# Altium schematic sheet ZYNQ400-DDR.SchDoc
size A3
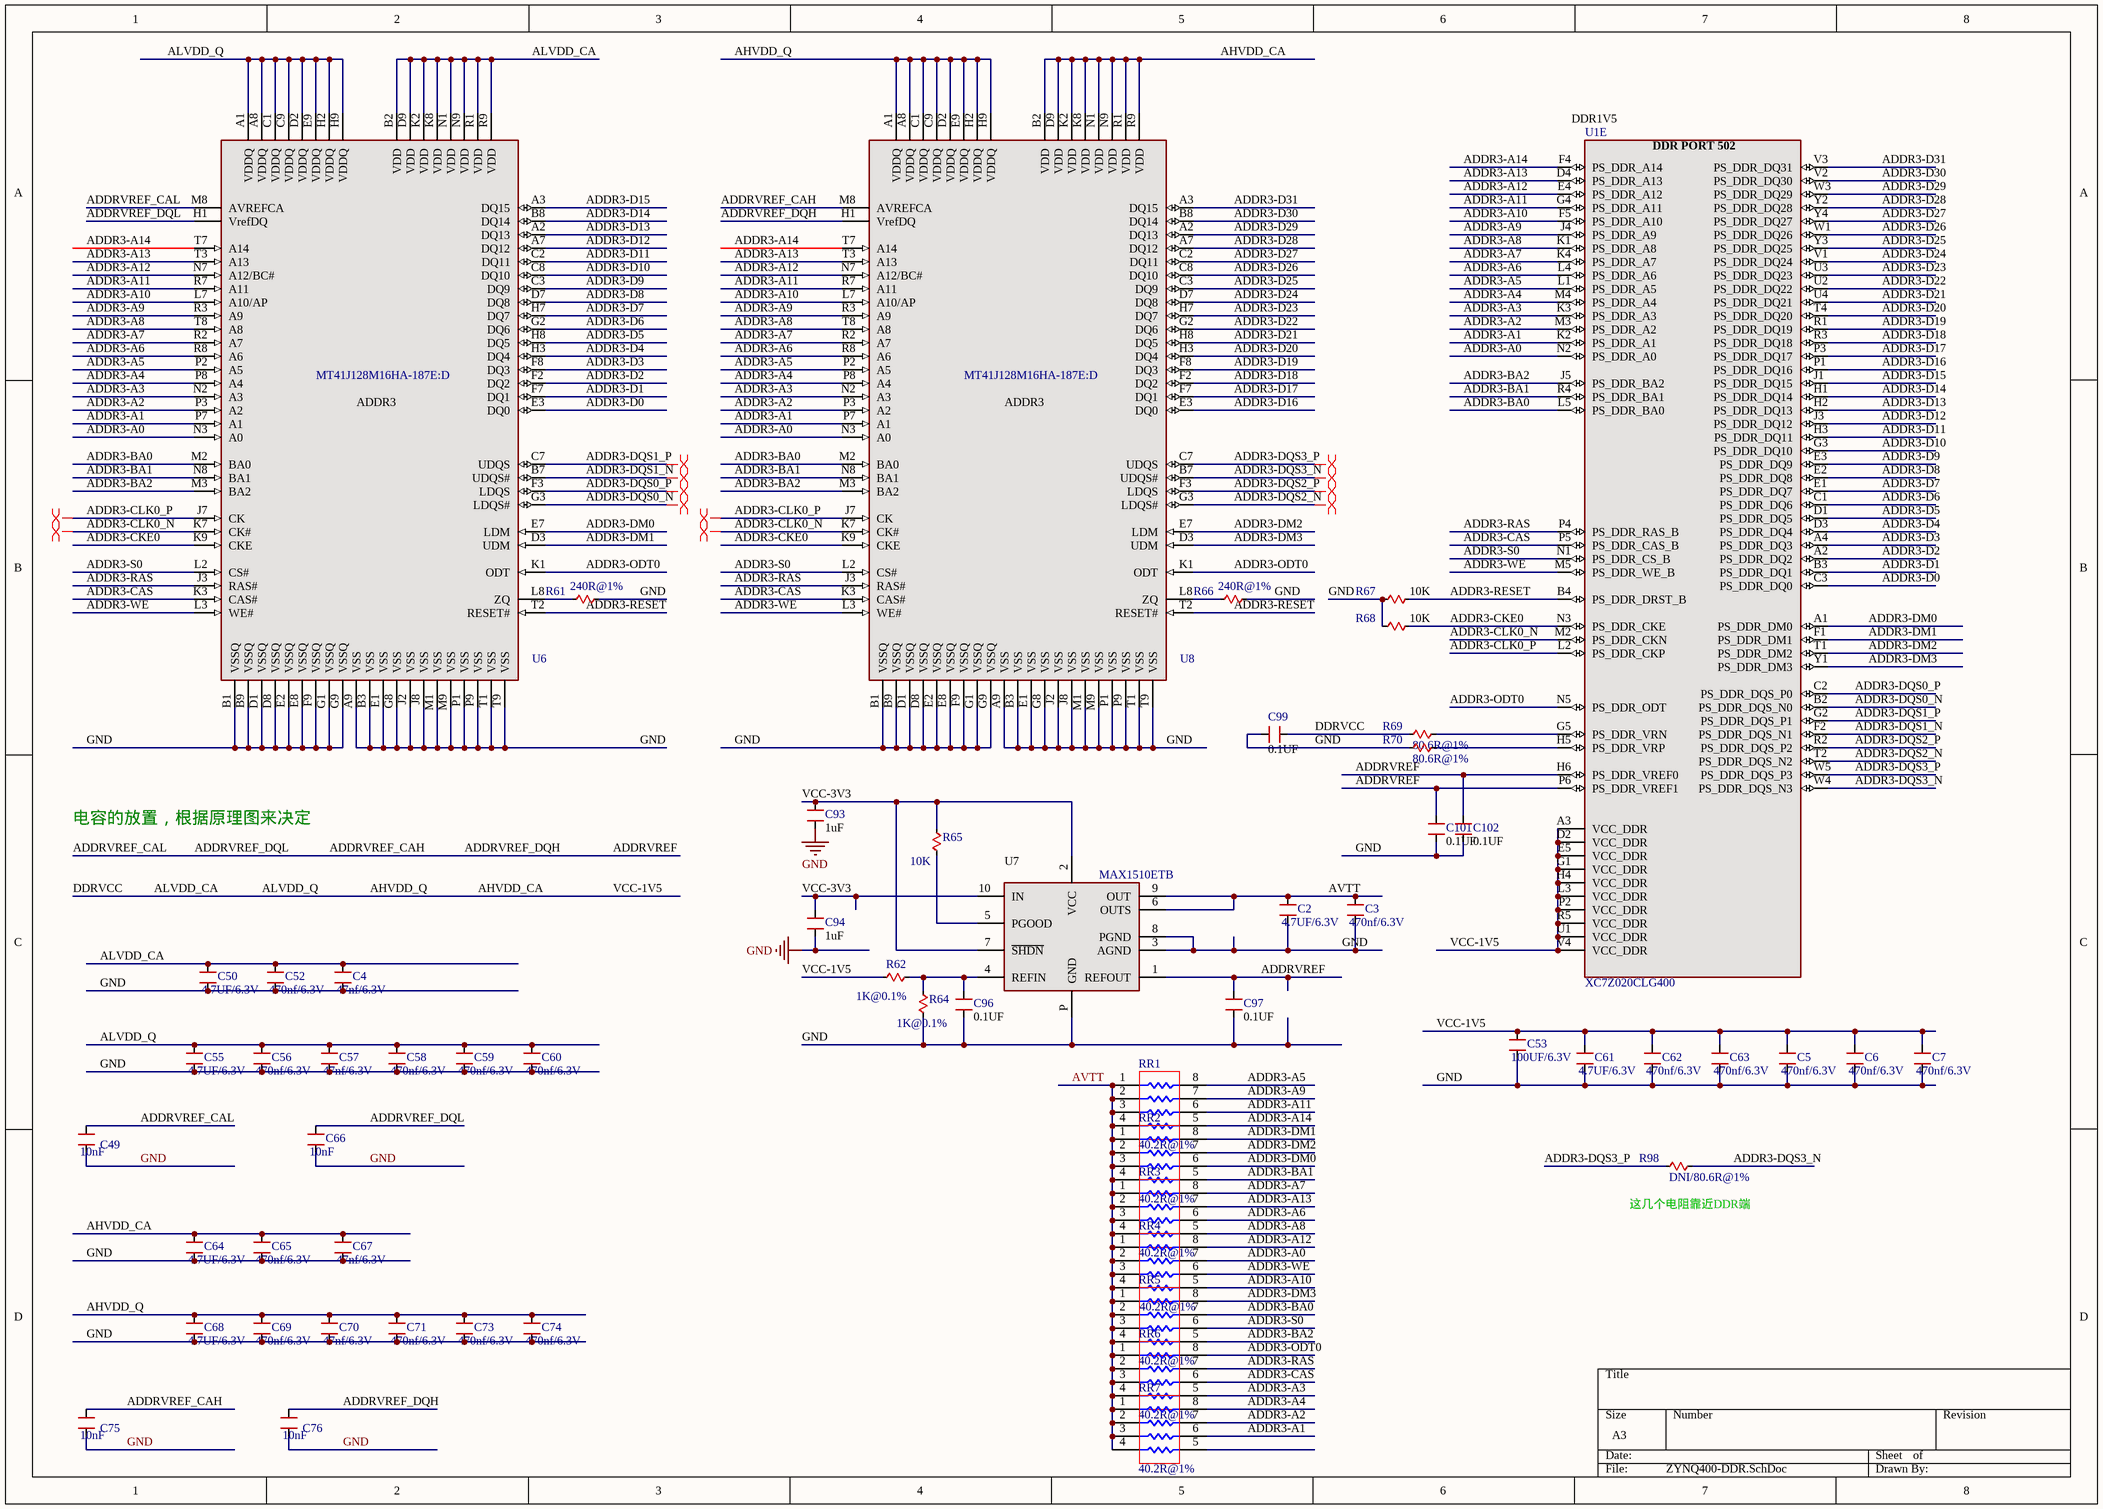
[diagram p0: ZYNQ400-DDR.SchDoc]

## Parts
C2  4.7UF/6.3V  [0402]
C3  470nf/6.3V  [0402]
C4  47nf/6.3V  [0402]
C5  470nf/6.3V  [0402]
C6  470nf/6.3V  [0402]
C7  470nf/6.3V  [0402]
C49  10nF  [0402]
C50  4.7UF/6.3V  [0402]
C52  470nf/6.3V  [0402]
C53  100UF/6.3V  [0805]
C55  4.7UF/6.3V  [0402]
C56  470nf/6.3V  [0402]
C57  47nf/6.3V  [0402]
C58  470nf/6.3V  [0402]
C59  470nf/6.3V  [0402]
C60  470nf/6.3V  [0402]
C61  4.7UF/6.3V  [0402]
C62  470nf/6.3V  [0402]
C63  470nf/6.3V  [0402]
C64  4.7UF/6.3V  [0402]
C65  470nf/6.3V  [0402]
C66  10nF  [0402]
C67  47nf/6.3V  [0402]
C68  4.7UF/6.3V  [0402]
C69  470nf/6.3V  [0402]
C70  47nf/6.3V  [0402]
C71  470nf/6.3V  [0402]
C73  470nf/6.3V  [0402]
C74  470nf/6.3V  [0402]
C75  10nF  [0402]
C76  10nF  [0402]
C93  1UF  [0402]
C94  1UF  [0402]
C96  0.1UF  [0402]
C97  0.1UF  [0402]
C99  0.1UF  [0402]
C101  0.1UF  [0402]
C102  0.1UF  [0402]
R61  240R@1%  [0402]
R62  1K@0.1%  [0402]
R64  1K@0.1%  [0402]
R65  10K  [0402]
R66  240R@1%  [0402]
R67  10K  [0402]
R68  10K  [0402]
R69  80.6R@1%  [0402]
R70  80.6R@1%  [0402]
R98  DNI/80.6R@1%  [0402]
RR1  40.2R@1%  [R0402*4]
RR2  40.2R@1%  [R0402*4]
RR3  40.2R@1%  [R0402*4]
RR4  40.2R@1%  [R0402*4]
RR5  40.2R@1%  [R0402*4]
RR6  40.2R@1%  [R0402*4]
RR7  40.2R@1%  [R0402*4]
U1  XC7Z020CLG400  [CLG400]  (part E of 9)
U6  MT41J128M16HA-187E:D  [FBGA96]
U7  MAX1510ETB  [TQFN]
U8  MT41J128M16HA-187E:D  [FBGA96]

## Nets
GND: C2.2 C3.2 C4.2 C5.2 C6.2 C7.2 C49.2 C50.2 C52.2 C53.2 C55.2 C56.2 C57.2 C58.2 C59.2 C60.2 C61.2 C62.2 C63.2 C64.2 C65.2 C66.2 C67.2 C68.2 C69.2 C70.2 C71.2 C73.2 C74.2 C75.2 C76.2 C93.2 C94.2 C96.1 C97.2 C99.1 C101.2 C102.2 R61.2 R64.2 R66.2 R67.2 R68.2 R70.1 U6.A9(VSS) U6.B1(VSSQ) U6.B3(VSS) U6.B9(VSSQ) U6.D1(VSSQ) U6.D8(VSSQ) U6.E1(VSS) U6.E2(VSSQ) U6.E8(VSSQ) U6.F9(VSSQ) U6.G1(VSSQ) U6.G8(VSS) U6.G9(VSSQ) U6.J2(VSS) U6.J8(VSS) U6.M1(VSS) U6.M9(VSS) U6.P1(VSS) U6.P9(VSS) U6.T1(VSS) U6.T9(VSS) U7.3(AGND) U7.8(PGND) U7.P(GND) U8.A9(VSS) U8.B1(VSSQ) U8.B3(VSS) U8.B9(VSSQ) U8.D1(VSSQ) U8.D8(VSSQ) U8.E1(VSS) U8.E2(VSSQ) U8.E8(VSSQ) U8.F9(VSSQ) U8.G1(VSSQ) U8.G8(VSS) U8.G9(VSSQ) U8.J2(VSS) U8.J8(VSS) U8.M1(VSS) U8.M9(VSS) U8.P1(VSS) U8.P9(VSS) U8.T1(VSS) U8.T9(VSS)
ADDR3-A0: RR4.7 U1.N2(PS_DDR_A0) U6.N3(A0) U8.N3(A0)
ADDR3-A1: RR7.6 U1.K2(PS_DDR_A1) U6.P7(A1) U8.P7(A1)
ADDR3-A2: RR7.7 U1.M3(PS_DDR_A2) U6.P3(A2) U8.P3(A2)
ADDR3-A3: RR6.5 U1.K3(PS_DDR_A3) U6.N2(A3) U8.N2(A3)
ADDR3-A4: RR7.8 U1.M4(PS_DDR_A4) U6.P8(A4) U8.P8(A4)
ADDR3-A5: RR1.8 U1.L1(PS_DDR_A5) U6.P2(A5) U8.P2(A5)
ADDR3-A6: RR3.6 U1.L4(PS_DDR_A6) U6.R8(A6) U8.R8(A6)
ADDR3-A7: RR3.8 U1.K4(PS_DDR_A7) U6.R2(A7) U8.R2(A7)
ADDR3-A8: RR3.5 U1.K1(PS_DDR_A8) U6.T8(A8) U8.T8(A8)
ADDR3-A9: RR1.7 U1.J4(PS_DDR_A9) U6.R3(A9) U8.R3(A9)
ADDR3-A10: RR4.5 U1.F5(PS_DDR_A10) U6.L7(A10/AP) U8.L7(A10/AP)
ADDR3-A11: RR1.6 U1.G4(PS_DDR_A11) U6.R7(A11) U8.R7(A11)
ADDR3-A12: RR4.8 U1.E4(PS_DDR_A12) U6.N7(A12/BC#) U8.N7(A12/BC#)
ADDR3-A13: RR3.7 U1.D4(PS_DDR_A13) U6.T3(A13) U8.T3(A13)
ADDR3-A14: RR1.5 U1.F4(PS_DDR_A14) U6.T7(A14) U8.T7(A14)
ADDR3-BA0: RR5.7 U1.L5(PS_DDR_BA0) U6.M2(BA0) U8.M2(BA0)
ADDR3-BA1: RR2.5 U1.R4(PS_DDR_BA1) U6.N8(BA1) U8.N8(BA1)
ADDR3-BA2: RR5.5 U1.J5(PS_DDR_BA2) U6.M3(BA2) U8.M3(BA2)
ADDR3-CAS: RR6.6 U1.P5(PS_DDR_CAS_B) U6.K3(CAS#) U8.K3(CAS#)
ADDR3-CKE0: R68.1 U1.N3(PS_DDR_CKE) U6.K9(CKE) U8.K9(CKE)
ADDR3-CLK0_N: U1.M2(PS_DDR_CKN) U6.K7(CK#) U8.K7(CK#)
ADDR3-CLK0_P: U1.L2(PS_DDR_CKP) U6.J7(CK) U8.J7(CK)
ADDR3-D0: U1.C3(PS_DDR_DQ0) U6.E3(DQ0)
ADDR3-D1: U1.B3(PS_DDR_DQ1) U6.F7(DQ1)
ADDR3-D2: U1.A2(PS_DDR_DQ2) U6.F2(DQ2)
ADDR3-D3: U1.A4(PS_DDR_DQ3) U6.F8(DQ3)
ADDR3-D4: U1.D3(PS_DDR_DQ4) U6.H3(DQ4)
ADDR3-D5: U1.D1(PS_DDR_DQ5) U6.H8(DQ5)
ADDR3-D6: U1.C1(PS_DDR_DQ6) U6.G2(DQ6)
ADDR3-D7: U1.E1(PS_DDR_DQ7) U6.H7(DQ7)
ADDR3-D8: U1.E2(PS_DDR_DQ8) U6.D7(DQ8)
ADDR3-D9: U1.E3(PS_DDR_DQ9) U6.C3(DQ9)
ADDR3-D10: U1.G3(PS_DDR_DQ10) U6.C8(DQ10)
ADDR3-D11: U1.H3(PS_DDR_DQ11) U6.C2(DQ11)
ADDR3-D12: U1.J3(PS_DDR_DQ12) U6.A7(DQ12)
ADDR3-D13: U1.H2(PS_DDR_DQ13) U6.A2(DQ13)
ADDR3-D14: U1.H1(PS_DDR_DQ14) U6.B8(DQ14)
ADDR3-D15: U1.J1(PS_DDR_DQ15) U6.A3(DQ15)
ADDR3-D16: U1.P1(PS_DDR_DQ16) U8.E3(DQ0)
ADDR3-D17: U1.P3(PS_DDR_DQ17) U8.F7(DQ1)
ADDR3-D18: U1.R3(PS_DDR_DQ18) U8.F2(DQ2)
ADDR3-D19: U1.R1(PS_DDR_DQ19) U8.F8(DQ3)
ADDR3-D20: U1.T4(PS_DDR_DQ20) U8.H3(DQ4)
ADDR3-D21: U1.U4(PS_DDR_DQ21) U8.H8(DQ5)
ADDR3-D22: U1.U2(PS_DDR_DQ22) U8.G2(DQ6)
ADDR3-D23: U1.U3(PS_DDR_DQ23) U8.H7(DQ7)
ADDR3-D24: U1.V1(PS_DDR_DQ24) U8.D7(DQ8)
ADDR3-D25: U1.Y3(PS_DDR_DQ25) U8.C3(DQ9)
ADDR3-D26: U1.W1(PS_DDR_DQ26) U8.C8(DQ10)
ADDR3-D27: U1.Y4(PS_DDR_DQ27) U8.C2(DQ11)
ADDR3-D28: U1.Y2(PS_DDR_DQ28) U8.A7(DQ12)
ADDR3-D29: U1.W3(PS_DDR_DQ29) U8.A2(DQ13)
ADDR3-D30: U1.V2(PS_DDR_DQ30) U8.B8(DQ14)
ADDR3-D31: U1.V3(PS_DDR_DQ31) U8.A3(DQ15)
ADDR3-DM0: RR2.6 U1.A1(PS_DDR_DM0) U6.E7(LDM)
ADDR3-DM1: RR2.8 U1.F1(PS_DDR_DM1) U6.D3(UDM)
ADDR3-DM2: RR2.7 U1.T1(PS_DDR_DM2) U8.E7(LDM)
ADDR3-DM3: RR5.8 U1.Y1(PS_DDR_DM3) U8.D3(UDM)
ADDR3-DQS0_N: U1.B2(PS_DDR_DQS_N0) U6.G3(LDQS#)
ADDR3-DQS0_P: U1.C2(PS_DDR_DQS_P0) U6.F3(LDQS)
ADDR3-DQS1_N: U1.F2(PS_DDR_DQS_N1) U6.B7(UDQS#)
ADDR3-DQS1_P: U1.G2(PS_DDR_DQS_P1) U6.C7(UDQS)
ADDR3-DQS2_N: U1.T2(PS_DDR_DQS_N2) U8.G3(LDQS#)
ADDR3-DQS2_P: U1.R2(PS_DDR_DQS_P2) U8.F3(LDQS)
ADDR3-DQS3_N: R98.2 U1.W4(PS_DDR_DQS_N3) U8.B7(UDQS#)
ADDR3-DQS3_P: R98.1 U1.W5(PS_DDR_DQS_P3) U8.C7(UDQS)
ADDR3-ODT0: RR6.8 U1.N5(PS_DDR_ODT) U6.K1(ODT) U8.K1(ODT)
ADDR3-RAS: RR6.7 U1.P4(PS_DDR_RAS_B) U6.J3(RAS#) U8.J3(RAS#)
ADDR3-RESET: R67.1 U1.B4(PS_DDR_DRST_B) U6.T2(RESET#) U8.T2(RESET#)
ADDR3-S0: RR5.6 U1.N1(PS_DDR_CS_B) U6.L2(CS#) U8.L2(CS#)
ADDR3-WE: RR4.6 U1.M5(PS_DDR_WE_B) U6.L3(WE#) U8.L3(WE#)
ADDRVREF: C49.1 C66.1 C75.1 C76.1 C97.1 C101.1 C102.1 U1.H6(PS_DDR_VREF0) U1.P6(PS_DDR_VREF1) U6.H1(VrefDQ) U6.M8(AVREFCA) U7.1(REFOUT) U8.H1(VrefDQ) U8.M8(AVREFCA)  [also labelled ADDRVREF_CAH, ADDRVREF_CAL, ADDRVREF_DQH, ADDRVREF_DQL]
AHVDD_CA: C4.1 C5.1 C6.1 C7.1 C50.1 C52.1 C53.1 C55.1 C56.1 C57.1 C58.1 C59.1 C60.1 C61.1 C62.1 C63.1 C64.1 C65.1 C67.1 C68.1 C69.1 C70.1 C71.1 C73.1 C74.1 C99.2 R62.1 R69.1 U1.A3(VCC_DDR) U1.D2(VCC_DDR) U1.E5(VCC_DDR) U1.G1(VCC_DDR) U1.H4(VCC_DDR) U1.L3(VCC_DDR) U1.P2(VCC_DDR) U1.R5(VCC_DDR) U1.U1(VCC_DDR) U1.V4(VCC_DDR) U6.A1(VDDQ) U6.A8(VDDQ) U6.B2(VDD) U6.C1(VDDQ) U6.C9(VDDQ) U6.D2(VDDQ) U6.D9(VDD) U6.E9(VDDQ) U6.H2(VDDQ) U6.H9(VDDQ) U6.K2(VDD) U6.K8(VDD) U6.N1(VDD) U6.N9(VDD) U6.R1(VDD) U6.R9(VDD) U8.A1(VDDQ) U8.A8(VDDQ) U8.B2(VDD) U8.C1(VDDQ) U8.C9(VDDQ) U8.D2(VDDQ) U8.D9(VDD) U8.E9(VDDQ) U8.H2(VDDQ) U8.H9(VDDQ) U8.K2(VDD) U8.K8(VDD) U8.N1(VDD) U8.N9(VDD) U8.R1(VDD) U8.R9(VDD)  [also labelled AHVDD_Q, ALVDD_CA, ALVDD_Q, DDRVCC, VCC-1V5]
AVTT: C2.1 C3.1 RR1.1 RR1.2 RR1.3 RR1.4 RR2.1 RR2.2 RR2.3 RR2.4 RR3.1 RR3.2 RR3.3 RR3.4 RR4.1 RR4.2 RR4.3 RR4.4 RR5.1 RR5.2 RR5.3 RR5.4 RR6.1 RR6.2 RR6.3 RR6.4 RR7.1 RR7.2 RR7.3 RR7.4 U7.6(OUTS) U7.9(OUT)
VCC-3V3: C93.1 C94.1 R65.1 U7.2(VCC) U7.7(~{SHDN}) U7.10(IN)
NetC96_2: C96.2 R62.2 R64.1 U7.4(REFIN)
NetR61_1: R61.1 U6.L8(ZQ)
NetR65_2: R65.2 U7.5(PGOOD)
NetR66_1: R66.1 U8.L8(ZQ)
NetR69_2: R69.2 U1.G5(PS_DDR_VRN)
NetR70_2: R70.2 U1.H5(PS_DDR_VRP)

Not connected (* = marked no-connect by the designer): RR7 5

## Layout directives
differential pair: ADDR3-CLK0_N, ADDR3-CLK0_P, ADDR3-DQS0_N, ADDR3-DQS0_P, ADDR3-DQS1_N, ADDR3-DQS1_P, ADDR3-DQS2_N, ADDR3-DQS2_P, ADDR3-DQS3_N, ADDR3-DQS3_P

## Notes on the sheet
- (near U1) DDR1V5
- 电容的放置，根据原理图来决定
- (near R98) 这几个电阻靠近DDR端

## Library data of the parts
C2-C7 C50 C52 C55-C65 C67-C71 C73 C74 C93 C94 C96 C97 C99 C101 C102 = CAPACITOR: Generic Capacitor
C49 C53 C66 C75 C76 = CAPACITOR: Generic Capacitor; Value: 0.1UF
R61 = RESISTOR: Generic Resistor; Value: 240R
R62 R64 = RESISTOR: Generic Resistor; Value: 1K
R65 = RESISTOR: Generic Resistor; Value: 10
R66 = RESISTOR: Generic Resistor; Value: 240
R67 R68 = RESISTOR: Generic Resistor
R69 R70 R98 = RESISTOR: Generic Resistor; Value: 80.6R
RR1-RR7 = Res -4: Isolated Resistor Network
U1 = XC7Z020-CLG400: Zynq 7000 FPGA 20 Die, in a CSG 484 Package; Manufacturer: Xilinx
U6 U8 = MT41JxxxMxx: DDR3 SDRAM 2Gb x4, x8, x16; Manufacturer: Micron
U7 = MAX1510: Low-Voltage, DDR Linear Regulators; Manufacturer: Maxim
